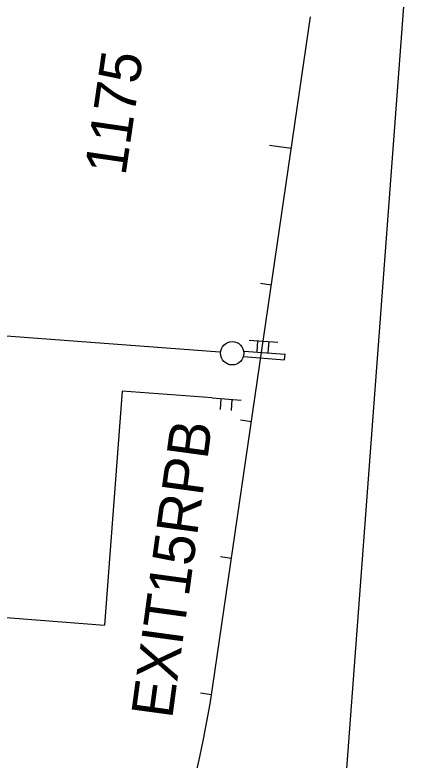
# Model space of a CAD drawing. Extents: x 2001876 to 2025694, y 804561 to 868938.
# Drawn here: x 2023139 to 2023436, y 808240 to 808780 of the extents above; entities that cross this region are included whole.
import ezdxf

# ---------------------------------------------------------------- set-up
doc = ezdxf.new("R2010")
doc.units = 0
for name, color, linetype in [('RD_EX_RW', 7, 'Continuous'), ('RD_PD_CLEAR ZONE', 7, 'Continuous'), ('RD_PD_OHS', 7, 'Continuous'), ('RD_Sketch2', 7, 'Continuous'), ('RD_TX_RoadID', 7, 'Continuous'), ('TR SN EXTRUDED PANEL SIGNS - GROUND MOUNTED', 7, 'Continuous'), ('TR SN EXTRUDED PANEL SIGNS- MOUNTED OVERHEAD', 7, 'Continuous')]:
    doc.layers.add(name, color=color, linetype=linetype)

msp = doc.modelspace()

# ---------------------------------------------------------------- linework, layer by layer
at = {"layer": 'RD_PD_CLEAR ZONE'}
for p, q in [((2023334.6, 807636.39), (2023651.04, 811857.7)), ((2023282.27, 808294.18), (2023352.99, 808778.77))]:
    msp.add_line(p, q, dxfattribs=at)
msp.add_arc((2022573.58, 808397.59), 716.2, 318.30772, 351.69747, dxfattribs=at)
at = {"layer": 'RD_PD_OHS'}
for p, q in [((2023308.5, 808544.59), (2023329.31, 808543.02)), ((2023314.74, 808544.12), (2023314.14, 808536.16)), ((2023322.74, 808543.52), (2023322.14, 808535.55)), ((2023304.64, 808536.6), (2023334.58, 808534.34)), ((2023304.42, 808532.66), (2023334.28, 808530.4)), ((2023334.28, 808530.4), (2023334.58, 808534.34))]:
    msp.add_line(p, q, dxfattribs=at)
msp.add_circle((2023296.31, 808535.08), 8.46, dxfattribs=at)
at = {"layer": 'RD_Sketch2'}
for p, q in [((2023339.07, 808683.34), (2023323.23, 808685.66)), ((2023324.63, 808584.39), (2023316.71, 808585.55)), ((2023310.19, 808485.44), (2023302.27, 808486.6)), ((2023295.75, 808386.49), (2023287.83, 808387.64)), ((2023281.27, 808287.54), (2023273.37, 808288.77))]:
    msp.add_line(p, q, dxfattribs=at)
at = {"layer": 'TR SN EXTRUDED PANEL SIGNS - GROUND MOUNTED'}
for p, q in [((2023122.5, 808548.48), (2023287.39, 808536.05)), ((2023216.49, 808507.66), (2023203.71, 808338.21)), ((2023281.88, 808502.73), (2023216.49, 808507.66)), ((2023281.88, 808502.73), (2023302.68, 808501.16)), ((2023288.11, 808502.26), (2023287.51, 808494.3)), ((2023296.12, 808501.66), (2023295.52, 808493.7)), ((2023067.56, 808348.48), (2023203.71, 808338.21))]:
    msp.add_line(p, q, dxfattribs=at)
at = {"layer": 'TR SN EXTRUDED PANEL SIGNS- MOUNTED OVERHEAD'}
for p, q in [((2023308.5, 808544.59), (2023329.31, 808543.02)), ((2023314.74, 808544.12), (2023314.14, 808536.16)), ((2023322.74, 808543.52), (2023322.14, 808535.55)), ((2023304.64, 808536.6), (2023334.58, 808534.34)), ((2023304.42, 808532.66), (2023334.28, 808530.4)), ((2023334.28, 808530.4), (2023334.58, 808534.34))]:
    msp.add_line(p, q, dxfattribs=at)
msp.add_circle((2023296.31, 808535.08), 8.46, dxfattribs=at)

# ---------------------------------------------------------------- texts
at = {"layer": 'RD_EX_RW'}
msp.add_text('1175', height=30, rotation=81.6975, dxfattribs=at).set_placement((2023218.89, 808663.12))
at = {"layer": 'RD_TX_RoadID'}
msp.add_text('EXIT15RPB', height=30, rotation=82.2444, dxfattribs=at).set_placement((2023252.72, 808269.75))

doc.saveas('drawing.dxf')
